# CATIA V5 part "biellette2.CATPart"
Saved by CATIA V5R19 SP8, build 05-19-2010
Part number: biellette2
Bounding box of the stored display mesh (mm): x 67 to 71, y 235.297 to 280.583, z 34.116 to 116.941
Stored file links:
  G:\EU_thinkMotion\CFAO_2010\MMS_groupe3\MMS_groupe3\A reprendre\amenand\amenand\biellette2.CATPart
  F:\thinkmotion CFAO v12.1\essuie_glace.CATProduct
  G:\EU_thinkMotion\CFAO_2010\MMS_groupe3\MMS_groupe3\A reprendre\amenand\amenand\squelette_biellette2.CATPart
  G:\EU_thinkMotion\CFAO_2010\MMS_groupe3\MMS_groupe3\A reprendre\amenand\amenand\bielle.CATPart
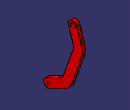
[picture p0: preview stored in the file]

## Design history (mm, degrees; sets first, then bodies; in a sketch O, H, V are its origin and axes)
Set1
  Plane1: linked copy from another document
  Point1: linked copy from another document
  Point2: linked copy from another document
  Line1 to Line3: linked copy from another document
  Point3: linked copy from another document
  Line4: linked copy from another document
Body1 (main body)
  Sketch1 on Plane1, origin (67, 222.8275, 0.0123), H (0, 1, 0), V (0, 0, 1)
    circle A1 centre (46.2382, 112.04) radius 2.5
    arc A2 centre (46.2382, 112.04) radius 5 from (50.9959, 113.5777) to (41.4806, 110.5024) ccw
    point P2 (46.2382, 112.04)
    circle A3 centre (17.456, 39.0895) radius 2
    point P3 (17.456, 39.0895)
    reference projected point E1 (17.456, 39.0895) from Point2
    arc A4 centre (17.456, 39.0895) radius 5 from (15.2853, 43.5938) to (19.6266, 34.5853) ccw
    point P4 (17.456, 39.0895)
    reference projected point E2 (17.456, 39.0895) from Point2
    line L1 (50.9959, 113.5777) -> (55.1772, 100.6404)
    line L2 (41.4806, 110.5024) -> (46.0002, 96.5182)
    line L3 (47.1801, 88.1933) -> (35.4079, 55.3166)
    line L4 (57.1555, 86.3884) -> (44.1946, 50.1919)
    reference projected line E3 (52.6515, 92.1967) -> (37.0095, 48.5127) from Line2
    line L5 (15.2853, 43.5938) -> (28.5009, 49.9626)
    reference projected line E4 (17.456, 39.0895) -> (37.0095, 48.5127) from Line3
    line L6 (19.6266, 34.5853) -> (33.7216, 41.3779)
    connectcurve C1
    connectcurve C2
    connectcurve C3
    connectcurve C4
    reference projected line E5 (46.2382, 112.04) -> (52.6515, 92.1967) from Line4
    reference projected point E6 (46.2382, 112.04) from Point3
    radius A1 = 2.5
    radius A2 = 5
    radius A3 = 2
    radius A4 = 5
    distance L3 L4 = 10
    distance C1 C2 = 10
    distance C3 C4 = 10
    coincidence: P3 E1, P4 E2, P2 E6
    tangency: L1 A2, L2 A2, L5 A4, L6 A4
    parallelism: L1 L2, E3 L4, L5 E4, L6 L5, E5 L1
    concentricity: A1 A2
  Pad1: profile Sketch1, direction (1, 0, 0), length 4
  Point4: linked copy from another document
